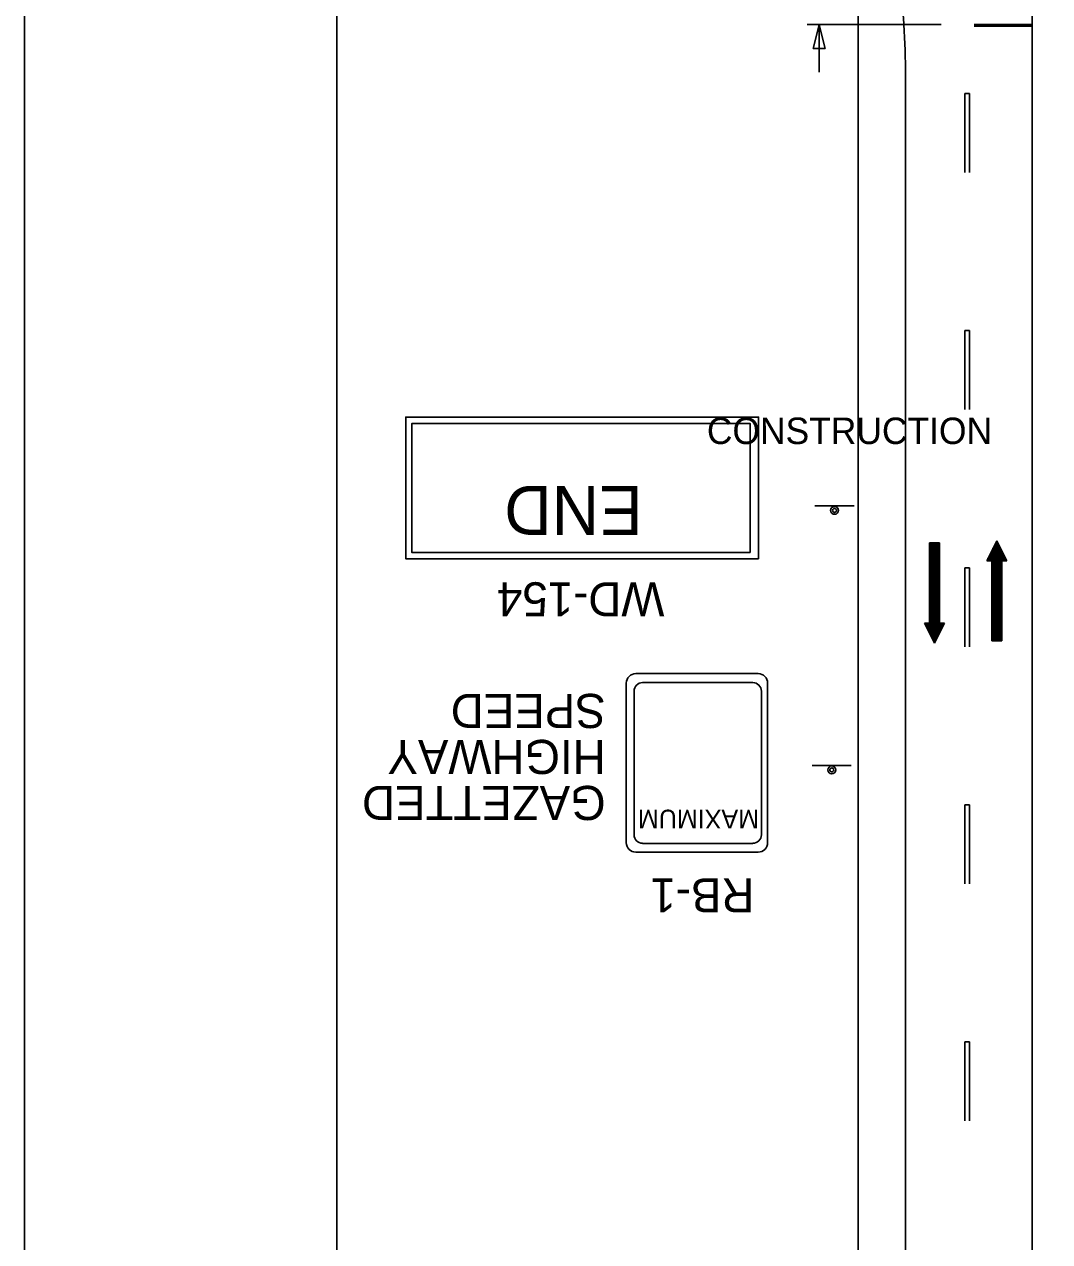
# Model space of a CAD drawing. Extents: x 2170 to 2386, y 134 to 413.
# Drawn here: x 2169.6 to 2232.4, y 216.1 to 290.7 of the extents above; entities that cross this region are included whole.
import ezdxf

# ---------------------------------------------------------------- set-up
doc = ezdxf.new("R2010")
doc.units = 0
for name, color, linetype in [('Level 10', 7, 'Continuous'), ('Level 2', 7, 'Continuous'), ('Level 44', 7, 'Continuous'), ('Level 5', 7, 'Continuous'), ('Level 60', 7, 'Continuous')]:
    doc.layers.add(name, color=color, linetype=linetype)

# ---------------------------------------------------------------- blocks, each defined once
blk = doc.blocks.new('END')
at = {"layer": 'Level 2'}
for points in [[(0, 8.676), (21.598, 8.676), (21.598, 0), (0, 0)], [(0.511, 8.287), (21.224, 8.287), (21.224, 0.397), (0.511, 0.397)]]:
    blk.add_lwpolyline(points, close=True, dxfattribs=at)
at = {"layer": 'Level 44'}
for s, height, rotation, p in [('END', 3, 359.99999, (7.085, 4.219)), ('CONSTRUCTION', 1.62, 179.99999, (3.164, 1.653))]:
    blk.add_text(s, height=height, rotation=rotation, dxfattribs=at).set_placement(p)

msp = doc.modelspace()

# ---------------------------------------------------------------- linework, layer by layer
at = {"layer": 'Level 10'}
for p, q in [((2220.644, 178.244), (2220.644, 313.635)), ((2231.288, 178.244), (2231.288, 293.208)), ((2225.727, 290.645), (2217.533, 290.645)), ((2218.259, 287.731), (2218.259, 290.633)), ((2231.288, 290.645), (2227.748, 290.645)), ((2231.288, 290.645), (2227.748, 290.645)), ((2231.288, 290.645), (2227.748, 290.645)), ((2231.288, 290.596), (2227.748, 290.596)), ((2231.288, 290.596), (2227.748, 290.596)), ((2231.288, 290.548), (2227.748, 290.548)), ((2223.547, 178.244), (2223.547, 287.501)), ((2225.022, 254.004), (2225.022, 258.912)), ((2225.635, 258.912), (2225.022, 258.912)), ((2225.022, 253.39), (2225.022, 258.912)), ((2225.099, 253.238), (2225.099, 258.912)), ((2225.176, 253.084), (2225.176, 258.912)), ((2225.252, 252.931), (2225.252, 258.912)), ((2225.328, 252.777), (2225.328, 258.912)), ((2225.405, 252.931), (2225.405, 258.912)), ((2225.483, 253.084), (2225.483, 258.912)), ((2225.559, 253.238), (2225.559, 258.912)), ((2225.635, 254.004), (2225.635, 258.912)), ((2225.635, 253.39), (2225.635, 258.912)), ((2229.13, 259.047), (2228.516, 257.82)), ((2228.9, 258.586), (2228.9, 252.912)), ((2228.975, 258.74), (2228.975, 252.912)), ((2229.054, 258.893), (2229.054, 252.912)), ((2229.13, 259.047), (2229.13, 252.912)), ((2229.13, 259.047), (2229.743, 257.82)), ((2229.206, 258.893), (2229.206, 252.912)), ((2229.283, 258.74), (2229.283, 252.912)), ((2229.36, 258.586), (2229.36, 252.912)), ((2228.516, 257.82), (2228.823, 257.82)), ((2228.593, 257.973), (2228.593, 257.82)), ((2228.669, 258.127), (2228.669, 257.82)), ((2228.746, 258.28), (2228.746, 257.82)), ((2228.823, 258.434), (2228.823, 252.912)), ((2228.823, 257.82), (2228.823, 252.912)), ((2229.436, 258.434), (2229.436, 252.912)), ((2229.436, 257.82), (2229.436, 252.912)), ((2229.436, 257.82), (2229.743, 257.82)), ((2229.513, 258.28), (2229.513, 257.82)), ((2229.59, 258.127), (2229.59, 257.82)), ((2229.667, 257.973), (2229.667, 257.82)), ((2225.328, 252.777), (2224.715, 254.004)), ((2225.022, 254.004), (2224.715, 254.004)), ((2224.792, 253.851), (2224.792, 254.004)), ((2224.869, 253.697), (2224.869, 254.004)), ((2224.945, 253.544), (2224.945, 254.004)), ((2225.328, 252.777), (2225.942, 254.004)), ((2225.942, 254.004), (2225.635, 254.004)), ((2225.713, 253.544), (2225.713, 254.004)), ((2225.789, 253.697), (2225.789, 254.004)), ((2225.865, 253.851), (2225.865, 254.004)), ((2228.823, 252.912), (2229.436, 252.912))]:
    msp.add_line(p, q, dxfattribs=at)
msp.add_lwpolyline([(2218.622, 289.182), (2218.259, 290.633), (2217.896, 289.182)], close=True, dxfattribs=at)
at = {"layer": 'Level 2'}
for p, q in [((2227.178, 286.424), (2227.178, 281.586)), ((2227.468, 286.424), (2227.178, 286.424)), ((2227.468, 281.586), (2227.468, 286.424)), ((2227.178, 271.91), (2227.178, 267.072)), ((2227.468, 271.91), (2227.178, 271.91)), ((2227.468, 267.072), (2227.468, 271.91)), ((2227.178, 257.396), (2227.178, 252.558)), ((2227.468, 257.396), (2227.178, 257.396)), ((2227.468, 252.558), (2227.468, 257.396)), ((2227.178, 242.882), (2227.178, 238.044)), ((2227.468, 242.882), (2227.178, 242.882)), ((2227.468, 238.044), (2227.468, 242.882)), ((2227.178, 228.368), (2227.178, 223.53)), ((2227.468, 228.368), (2227.178, 228.368)), ((2227.468, 223.53), (2227.468, 228.368))]:
    msp.add_line(p, q, dxfattribs=at)
for points in [[(2214.556, 257.941), (2192.958, 257.941), (2192.958, 266.617), (2214.556, 266.617)], [(2214.045, 258.33), (2193.332, 258.33), (2193.332, 266.22), (2214.045, 266.22)]]:
    msp.add_lwpolyline(points, close=True, dxfattribs=at)
at = {"layer": 'Level 44'}
for p, q in [((2218, 261.173), (2220.397, 261.173)), ((2207.036, 250.915), (2214.532, 250.915)), ((2207.458, 250.36), (2214.204, 250.36)), ((2206.457, 240.563), (2206.457, 250.333)), ((2206.937, 241.044), (2206.937, 249.839)), ((2214.724, 249.841), (2214.724, 249.839)), ((2214.724, 249.839), (2214.724, 241.044)), ((2215.11, 250.337), (2215.11, 250.333)), ((2215.11, 250.333), (2215.11, 240.563)), ((2217.833, 245.288), (2220.229, 245.288)), ((2214.532, 239.984), (2207.036, 239.984)), ((2214.204, 240.524), (2207.458, 240.524))]:
    msp.add_line(p, q, dxfattribs=at)
for centre, radius in [((2219.204, 260.904), 0.24), ((2219.204, 260.904), 0.12), ((2219.036, 245.019), 0.24), ((2219.036, 245.019), 0.12)]:
    msp.add_circle(centre, radius, dxfattribs=at)
for centre, radius, start, end in [((2207.036, 250.335), 0.578, 90, 179.99999), ((2207.458, 249.841), 0.52, 90, 179.99999), ((2214.204, 249.841), 0.52, 360, 89.99999), ((2214.531, 250.335), 0.578, 360, 89.99999), ((2207.458, 241.046), 0.52, 179.99999, 269.99999), ((2214.204, 241.046), 0.52, 270, 359.99999), ((2207.036, 240.563), 0.578, 179.99999, 269.99999), ((2214.531, 240.563), 0.578, 270, 359.99999)]:
    msp.add_arc(centre, radius, start, end, dxfattribs=at)
at = {"layer": 'Level 5'}
msp.add_arc((2173.547, 287.501), 50, 0, 7.19678, dxfattribs=at)
at = {"layer": 'Level 60'}
for points in [[(2169.622, 412.757), (2385.622, 412.757), (2385.622, 133.757), (2169.622, 133.757)], [(2188.748, 401.948), (2375.622, 401.948), (2375.622, 144.566), (2188.748, 144.566)]]:
    msp.add_lwpolyline(points, close=True, dxfattribs=at)

# ---------------------------------------------------------------- block references
at = {"layer": 'Level 2', "rotation": 180}
msp.add_blockref('END', (2214.556, 266.617), dxfattribs=at)

# ---------------------------------------------------------------- texts
at = {"layer": 'Level 10'}
for s, p in [('WD-154', (2208.795, 256.503)), ('RB-1', (2214.301, 238.385))]:
    msp.add_text(s, height=2.09, rotation=180, dxfattribs=at).set_placement(p)
at = {"layer": 'Level 44'}
for s, height, rotation, p in [('CONSTRUCTION', 1.62023, 359.99999, (2211.393, 264.965)), ('MAXIMUM', 1.1467, 180, (2214.583, 242.583))]:
    msp.add_text(s, height=height, rotation=rotation, dxfattribs=at).set_placement(p)
at = {"layer": 'Level 5'}
for s, p in [('SPEED', (2205.197, 249.674)), ('HIGHWAY', (2205.197, 246.859)), ('GAZETTED', (2205.197, 244.043))]:
    msp.add_text(s, height=2.09, rotation=180, dxfattribs=at).set_placement(p)

doc.saveas('drawing.dxf')
